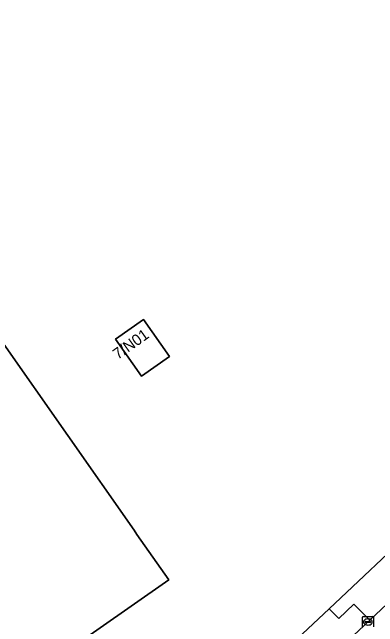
# Model space of a CAD drawing. Extents: x 156702 to 158052, y 387630 to 388992.
# Drawn here: x 157434.5 to 157467.5, y 388207.7 to 388263.2 of the extents above; entities that cross this region are included whole.
import ezdxf

# ---------------------------------------------------------------- set-up
doc = ezdxf.new("R2010")
doc.units = 0
for name, color, linetype in [('IMGEO_Berm_groen', 7, 'Continuous'), ('IMGEO_Erf', 7, 'Continuous'), ('IMGEO_Hek', 7, 'Continuous'), ('IMGEO_Kolk', 7, 'Continuous'), ('IMGEO_Pand', 7, 'Continuous'), ('IMGEO_Pand_nummerreeks', 7, 'Continuous'), ('IMGEO_Rijbaan_lokaal_gesloten', 7, 'Continuous'), ('IMGEO_Rijbaan_lokaal_open', 7, 'Continuous')]:
    doc.layers.add(name, color=color, linetype=linetype)

msp = doc.modelspace()

# ---------------------------------------------------------------- linework, layer by layer
at = {"layer": 'IMGEO_Berm_groen'}
msp.add_lwpolyline([(157480.113, 388220.87), (157479.095, 388222.004), (157480.103, 388222.956), (157478.926, 388224.264), (157463.105, 388209.35), (157463.965, 388208.467), (157465.321, 388209.774), (157466.756, 388208.315)], close=True, dxfattribs=at)
at = {"layer": 'IMGEO_Erf'}
msp.add_lwpolyline([(157304.594, 388111.931), (157309.704, 388107.668), (157345.604, 388078.857), (157350.282, 388079.607), (157353.239, 388083.252), (157357.392, 388088.42), (157376.693, 388112.497), (157380.893, 388117.749), (157391.144, 388130.462), (157404.098, 388146.633), (157406.558, 388149.7), (157418.329, 388164.322), (157428.032, 388175.523), (157430.343, 388177.94), (157441.633, 388189.119), (157442.935, 388190.379), (157453.889, 388200.705), (157463.105, 388209.35), (157478.926, 388224.264), (157484.402, 388229.388), (157504.128, 388247.959), (157518.512, 388268.247), (157504.449, 388292.394)], dxfattribs=at)
for points in [[(157412.967, 388262.946), (157433.516, 388233.555), (157445.484, 388216.437), (157445.75, 388216.056), (157448.615, 388211.959), (157432.502, 388200.695), (157417.472, 388190.105), (157414.414, 388194.477), (157410.424, 388191.692), (157410.258, 388191.93), (157407.56, 388195.791), (157386.768, 388225.543), (157377.849, 388238.342)], [(157446.336, 388235.488), (157448.69, 388232.125), (157446.148, 388230.373), (157443.802, 388233.705)]]:
    msp.add_lwpolyline(points, close=True, dxfattribs=at)
at = {"layer": 'IMGEO_Hek'}
msp.add_lwpolyline([(157478.926, 388224.264), (157463.105, 388209.35)], dxfattribs=at)
at = {"layer": 'IMGEO_Kolk'}
for p, q in [((157466.094, 388207.724), (157466.094, 388208.576)), ((157466.169, 388208.65), (157467.021, 388208.65)), ((157466.353, 388208.144), (157466.353, 388208.156)), ((157466.396, 388208.193), (157466.794, 388208.193)), ((157466.582, 388208.43), (157466.607, 388208.43)), ((157466.837, 388208.156), (157466.837, 388208.144)), ((157467.095, 388208.576), (157467.095, 388207.724)), ((157466.791, 388208.107), (157466.393, 388208.107)), ((157466.605, 388207.87), (157466.58, 388207.87))]:
    msp.add_line(p, q, dxfattribs=at)
for points in [[(157466.094, 388207.724), (157466.094, 388208.576)], [(157466.169, 388208.65), (157467.021, 388208.65)], [(157467.095, 388208.576), (157467.095, 388207.724)]]:
    msp.add_lwpolyline(points, dxfattribs=at)
for centre, radius, start, end in [((157466.171, 388208.574), 0.0765, 91.552, 178.448), ((157466.171, 388208.574), 0.0765, 91.552, 178.448), ((157466.393, 388208.153), 0.0403, 85.8775, 175.7526), ((157466.798, 388208.155), 0.0386, 1.7309, 96.639), ((157467.019, 388208.574), 0.0765, 1.552, 88.448), ((157467.019, 388208.574), 0.0765, 1.552, 88.448), ((157466.39, 388208.143), 0.0366, 178.938, 274.7102), ((157466.794, 388208.15), 0.043, 264.8664, 352.4533)]:
    msp.add_arc(centre, radius, start, end, dxfattribs=at)
for centre, major_axis, ratio, start_param, end_param in [((157466.581, 388208.15), (-0.387, 0.002), 0.722429, 4.712389, 7.853982), ((157466.606, 388208.15), (-0.39, 0.002), 0.717154, 1.570796, 4.712389)]:
    msp.add_ellipse(centre, major_axis=major_axis, ratio=ratio, start_param=start_param, end_param=end_param, dxfattribs=at)
at = {"layer": 'IMGEO_Pand'}
for points in [[(157433.516, 388233.555), (157412.967, 388262.946), (157377.849, 388238.342), (157386.768, 388225.543), (157407.56, 388195.791), (157410.258, 388191.93), (157410.424, 388191.692), (157414.414, 388194.477), (157417.472, 388190.105), (157432.502, 388200.695), (157448.615, 388211.959), (157445.75, 388216.056), (157445.484, 388216.437)], [(157446.148, 388230.373), (157448.69, 388232.125), (157446.336, 388235.488), (157443.802, 388233.705)]]:
    msp.add_lwpolyline(points, close=True, dxfattribs=at)
at = {"layer": 'IMGEO_Rijbaan_lokaal_gesloten'}
msp.add_lwpolyline([(157523.657, 388263.239), (157519.096, 388257.304), (157518.699, 388257.179), (157487.432, 388227.724), (157480.113, 388220.87), (157466.756, 388208.315), (157454.801, 388197.046), (157444.911, 388187.668), (157443.597, 388186.422), (157441.773, 388184.676)], dxfattribs=at)
at = {"layer": 'IMGEO_Rijbaan_lokaal_open'}
msp.add_lwpolyline([(157453.889, 388200.705), (157454.714, 388199.862), (157453.378, 388198.514), (157454.801, 388197.046), (157466.756, 388208.315), (157465.321, 388209.774), (157463.965, 388208.467), (157463.105, 388209.35)], close=True, dxfattribs=at)

# ---------------------------------------------------------------- texts
at = {"layer": 'IMGEO_Pand_nummerreeks'}
msp.add_text('7/N01', height=1, rotation=35.5377, dxfattribs=at).set_placement((157444.022, 388231.819))

doc.saveas('drawing.dxf')
